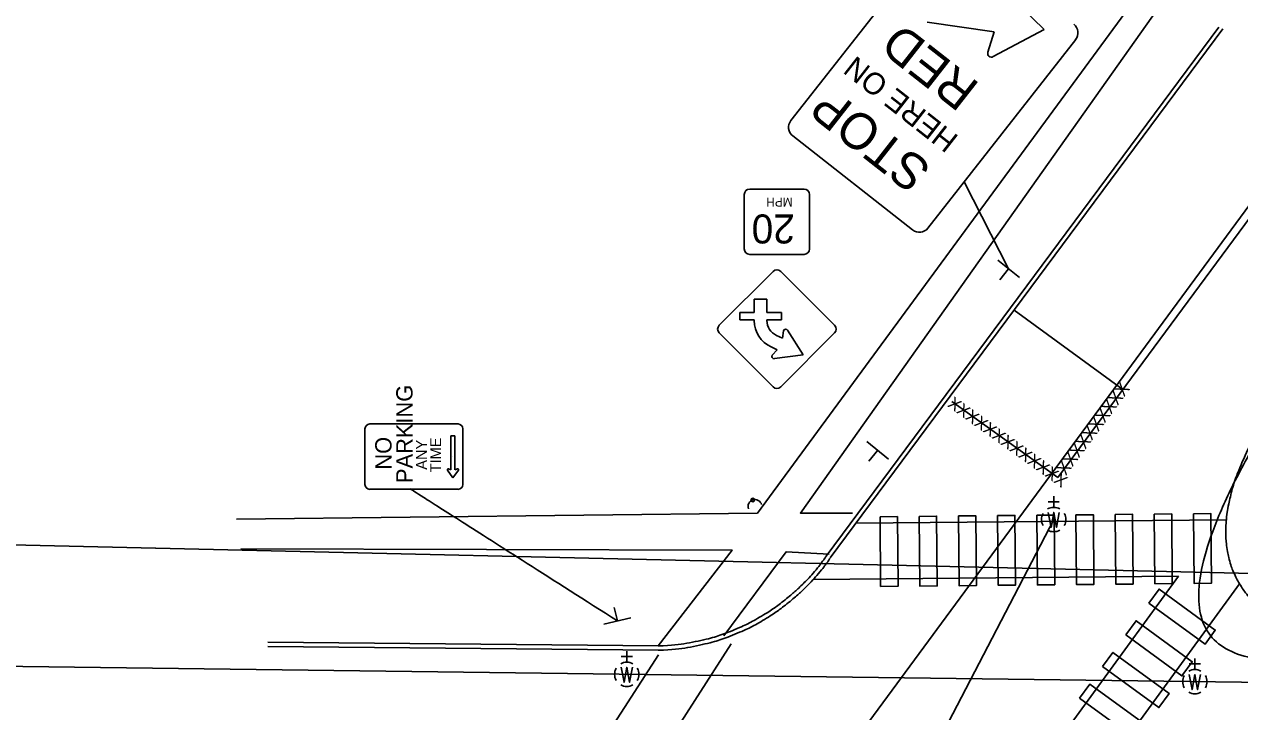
# Model space of a CAD drawing. Extents: x 108269 to 109415, y 548506 to 548874.
# Drawn here: x 108929.7 to 109069.3, y 548713.3 to 548792.2 of the extents above; entities that cross this region are included whole.
import ezdxf

# ---------------------------------------------------------------- set-up
doc = ezdxf.new("R2010")
doc.units = 0
for name, color, linetype in [('Default', 7, 'Continuous'), ('PM_P_Crosswalk', 7, 'Continuous'), ('PM_P_Stop_Line', 7, 'Continuous'), ('SH_Data', 7, 'Continuous'), ('SH_Text', 7, 'Continuous'), ('SN_P_Post', 7, 'Continuous'), ('SN_P_Signs', 7, 'Continuous'), ('SN_P_Text', 7, 'Continuous'), ('SN_X_Post', 7, 'Continuous'), ('SN_X_Public', 7, 'Continuous')]:
    doc.layers.add(name, color=color, linetype=linetype)

msp = doc.modelspace()

# ---------------------------------------------------------------- linework, layer by layer
at = {"layer": 'Default'}
for p, q in [((109022.45, 548706.36), (109144.06, 548871.47)), ((109066.95, 548791.92), (109021.83, 548731.18)), ((109067.41, 548791.7), (109022.29, 548730.97)), ((109048.43, 548740.21), (109081.46, 548784.86)), ((109036.25, 548748.92), (109048.43, 548740.21)), ((109047.97, 548736.78), (109047.97, 548738.05)), ((109048.61, 548737.41), (109047.34, 548737.41)), ((109013.34, 548668.7), (109047.97, 548735.38)), ((109067.8, 548735.36), (109025.26, 548734.96)), ((109047.97, 548735.38), (109047.97, 548735.38)), ((108915.58, 548732.79), (109082.36, 548728.91)), ((109062.3, 548728.89), (109020.34, 548728.49)), ((109062.3, 548728.89), (109034.32, 548690.49)), ((109069.3, 548728.02), (109040.71, 548688.79)), ((108957.71, 548721.32), (109002.57, 548720.87)), ((108957.7, 548720.82), (109002.57, 548720.37)), ((109002.56, 548719.87), (108979.51, 548684.16)), ((109010.93, 548721.11), (108986.03, 548682.43)), ((108998.93, 548719.01), (108998.93, 548720.28)), ((108918.1, 548718.65), (109208.22, 548714.91)), ((108999.57, 548719.65), (108998.3, 548719.65)), ((109064.81, 548718.8), (109063.54, 548718.8)), ((109064.18, 548718.17), (109064.18, 548719.44)), ((108998.93, 548717.61), (108998.93, 548717.61)), ((109064.18, 548716.77), (109064.18, 548716.77))]:
    msp.add_line(p, q, dxfattribs=at)
for points in [[(108954.1, 548735.42), (109013.93, 548736.13), (109058.46, 548796.73)], [(109060.66, 548795.08), (109018.88, 548736.13), (109024.87, 548736.13)], [(109047.34, 548736.2), (109047.66, 548734.47), (109047.97, 548736.2), (109048.29, 548734.47), (109048.61, 548736.2)], [(108954.62, 548732.02), (109011.02, 548731.87), (109002.55, 548720.87)], [(109010.08, 548722.03), (109017.23, 548731.66), (109022.18, 548731.4)], [(108998.3, 548718.43), (108998.62, 548716.71), (108998.93, 548718.43), (108999.25, 548716.71), (108999.57, 548718.43)], [(109063.54, 548717.59), (109063.86, 548715.86), (109064.18, 548717.59), (109064.5, 548715.86), (109064.81, 548717.59)]]:
    msp.add_lwpolyline(points, dxfattribs=at)
msp.add_circle((109013.41, 548737.63), 0.2, dxfattribs=at)
for centre, radius, start, end in [((109013.66, 548736.87), 0.8, 17.6188, 197.6188), ((109047.97, 548735.38), 1.4, 60.0184, 120.0157), ((109047.97, 548735.38), 1.4, 150.0184, 209.9816), ((109047.97, 548735.38), 1.4, 330.0184, 29.9816), ((109047.97, 548735.38), 1.4, 239.9843, 299.9816), ((108998.93, 548717.61), 1.4, 60.0184, 120.0157), ((108998.93, 548717.61), 1.4, 150.0184, 209.9816), ((108998.93, 548717.61), 1.4, 330.0184, 29.9816), ((109064.18, 548716.77), 1.4, 150.0184, 209.9816), ((109064.18, 548716.77), 1.4, 60.0184, 120.0157), ((109064.18, 548716.77), 1.4, 330.0184, 29.9816), ((108998.93, 548717.61), 1.4, 239.9843, 299.9816), ((109064.18, 548716.77), 1.4, 239.9843, 299.9816)]:
    msp.add_arc(centre, radius, start, end, dxfattribs=at)
for points, degree in [([(109072.63, 548746.68), (109055.79, 548718.85), (109092.93, 548719.74), (109092.93, 548719.74)], 2), ([(109072.2, 548746.94), (109071.14, 548745.18), (109070.28, 548743.54), (109068.95, 548740.44), (109068.48, 548739), (109068.02, 548736.97), (109067.9, 548736.31), (109067.76, 548735.05), (109067.73, 548734.44), (109067.74, 548733.27), (109067.78, 548732.7), (109067.93, 548731.62), (109068.05, 548731.09), (109068.33, 548730.09), (109068.51, 548729.61), (109068.92, 548728.69), (109069.15, 548728.25), (109069.67, 548727.42), (109069.96, 548727.02), (109070.58, 548726.26), (109070.91, 548725.9), (109071.96, 548724.89), (109072.73, 548724.28), (109074.39, 548723.2), (109075.27, 548722.73), (109077.1, 548721.9), (109078.05, 548721.54), (109079.96, 548720.92), (109080.92, 548720.66), (109082.82, 548720.21), (109083.76, 548720.03), (109085.57, 548719.74), (109086.44, 548719.62), (109088.89, 548719.36), (109090.29, 548719.28), (109091.8, 548719.24), (109092.2, 548719.23), (109092.63, 548719.23), (109092.74, 548719.23), (109092.85, 548719.24), (109092.88, 548719.24), (109092.91, 548719.24), (109092.92, 548719.24), (109092.93, 548719.24), (109092.93, 548719.24), (109092.94, 548719.24), (109092.94, 548719.24), (109092.94, 548719.24)], 3), ([(109021.83, 548731.18), (109021.83, 548731.18), (109021.83, 548731.18), (109021.83, 548731.18), (109021.83, 548731.18), (109021.83, 548731.17), (109021.82, 548731.17), (109021.81, 548731.14), (109021.79, 548731.11), (109021.72, 548731), (109021.64, 548730.9), (109021.35, 548730.49), (109021.06, 548730.1), (109020.28, 548729.16), (109019.79, 548728.61), (109018.6, 548727.43), (109017.91, 548726.8), (109016.31, 548725.53), (109015.42, 548724.9), (109013.41, 548723.7), (109012.31, 548723.14), (109009.89, 548722.16), (109008.57, 548721.74), (109005.72, 548721.12), (109004.18, 548720.92), (109002.53, 548720.87)], 3), ([(109021.83, 548731.18), (109021.83, 548731.18), (109021.83, 548731.18), (109021.83, 548731.18)], 2), ([(109002.55, 548720.37), (109004.24, 548720.42), (109005.82, 548720.63), (109008.76, 548721.27), (109010.11, 548721.7), (109012.6, 548722.72), (109013.74, 548723.3), (109015.79, 548724.54), (109016.7, 548725.2), (109018.33, 548726.5), (109019.03, 548727.15), (109020.23, 548728.35), (109020.73, 548728.91), (109021.52, 548729.87), (109021.81, 548730.26), (109022.09, 548730.66), (109022.16, 548730.76), (109022.22, 548730.87), (109022.24, 548730.89), (109022.25, 548730.91), (109022.26, 548730.92), (109022.26, 548730.92), (109022.26, 548730.92), (109022.26, 548730.92), (109022.26, 548730.92), (109022.26, 548730.92), (109022.26, 548730.92), (109022.26, 548730.92), (109022.26, 548730.92)], 3), ([(109022.26, 548730.92), (109022.26, 548730.92), (109022.26, 548730.92), (109022.26, 548730.92)], 2)]:
    msp.add_open_spline(points, degree=degree, dxfattribs=at)
at = {"layer": 'PM_P_Crosswalk'}
for points in [[(109028.02, 548735.7), (109030.02, 548735.72), (109030.09, 548727.72), (109028.09, 548727.71)], [(109032.52, 548735.75), (109034.52, 548735.77), (109034.59, 548727.77), (109032.59, 548727.75)], [(109037.02, 548735.79), (109039.02, 548735.81), (109039.09, 548727.81), (109037.09, 548727.79)], [(109041.52, 548735.83), (109043.52, 548735.85), (109043.59, 548727.85), (109041.59, 548727.84)], [(109046.02, 548735.88), (109048.02, 548735.9), (109048.09, 548727.9), (109046.09, 548727.88)], [(109050.52, 548735.92), (109052.52, 548735.94), (109052.59, 548727.94), (109050.59, 548727.92)], [(109055.02, 548735.96), (109057.02, 548735.98), (109057.09, 548727.98), (109055.09, 548727.97)], [(109059.52, 548736.01), (109061.52, 548736.03), (109061.59, 548728.03), (109059.59, 548728.01)], [(109064.02, 548736.05), (109066.02, 548736.07), (109066.09, 548728.07), (109064.09, 548728.05)], [(109058.89, 548725.78), (109060.07, 548727.4), (109066.53, 548722.69), (109065.35, 548721.07)], [(109056.24, 548722.15), (109057.42, 548723.76), (109063.88, 548719.05), (109062.7, 548717.44)], [(109053.59, 548718.51), (109054.77, 548720.13), (109061.23, 548715.41), (109060.05, 548713.8)], [(109050.94, 548714.87), (109052.12, 548716.49), (109058.58, 548711.78), (109057.4, 548710.16)]]:
    msp.add_lwpolyline(points, close=True, dxfattribs=at)
at = {"layer": 'PM_P_Stop_Line'}
msp.add_line((109043.43, 548759.43), (109055.9, 548750.31), dxfattribs=at)
at = {"layer": 'SH_Data'}
msp.add_open_spline([(108997.85, 548723.74), (108974.15, 548738.85), (108974.15, 548738.85), (108974.15, 548738.85)], degree=2, dxfattribs=at)
at = {"layer": 'SH_Text'}
msp.add_line((109042.79, 548764.15), (109037.69, 548774.16), dxfattribs=at)
at = {"layer": 'SN_P_Post'}
for p, q in [((109041.54, 548765.15), (109044.04, 548763.15)), ((109042.79, 548764.15), (109041.79, 548762.9)), ((109042.79, 548764.15), (109042.79, 548764.15))]:
    msp.add_line(p, q, dxfattribs=at)
at = {"layer": 'SN_P_Signs'}
for p, q in [((109034.75, 548802.82), (109017.78, 548781.18)), ((109042.11, 548796.29), (109046.86, 548791.65)), ((109041.14, 548791.37), (109033.42, 548792.46)), ((109040.41, 548789.02), (109041.14, 548791.37)), ((109046.86, 548791.65), (109041.01, 548788.52)), ((109033.52, 548768.84), (109050.49, 548790.48)), ((109017.99, 548779.42), (109031.76, 548768.63)), ((109033.51, 548768.84), (109033.52, 548768.84))]:
    msp.add_line(p, q, dxfattribs=at)
for centre, radius, start, end in [((109049.5, 548791.25), 1.25, 321.8936, 51.8936), ((109040.8, 548788.88), 0.417, 159.8639, 300.4822), ((109018.76, 548780.41), 1.25, 141.8936, 231.8936), ((109032.53, 548769.61), 1.25, 231.8936, 321.8936)]:
    msp.add_arc(centre, radius, start, end, dxfattribs=at)
at = {"layer": 'SN_X_Post'}
for p, q in [((109026.52, 548744.34), (109029.01, 548742.33)), ((109027.76, 548743.34), (109026.75, 548742.09)), ((109027.76, 548743.34), (109027.76, 548743.34)), ((108999.4, 548724.11), (108996.29, 548723.38)), ((108997.85, 548723.74), (108997.48, 548725.3)), ((108997.85, 548723.74), (108997.85, 548723.74))]:
    msp.add_line(p, q, dxfattribs=at)
at = {"layer": 'SN_X_Public'}
for p, q in [((109019.3, 548773.32), (109013.05, 548773.32)), ((109012.42, 548772.7), (109012.42, 548766.45)), ((109019.92, 548766.45), (109019.92, 548772.7)), ((109013.05, 548765.82), (109019.3, 548765.82)), ((109015.03, 548760.68), (109013.57, 548760.68)), ((109013.57, 548760.68), (109013.57, 548759.15)), ((109015.03, 548759.15), (109015.03, 548760.68)), ((109013.57, 548759.15), (109011.9, 548759.15)), ((109011.9, 548759.15), (109011.9, 548758.32)), ((109016.7, 548759.15), (109015.03, 548759.15)), ((109016.7, 548758.32), (109016.7, 548759.15)), ((109011.9, 548758.32), (109013.57, 548758.32)), ((109013.57, 548758.32), (109013.57, 548758.22)), ((109015.03, 548758.22), (109015.03, 548758.32)), ((109015.03, 548758.32), (109016.7, 548758.32)), ((109016.82, 548756.19), (109016.12, 548756.51)), ((109016.94, 548757.04), (109016.82, 548756.19)), ((109019.2, 548754.29), (109017.4, 548757.11)), ((109015.51, 548755.19), (109016.19, 548754.87)), ((109016.19, 548754.87), (109015.64, 548754.24)), ((109015.89, 548753.85), (109019.2, 548754.29)), ((109015.89, 548753.85), (109015.89, 548753.85)), ((108979.2, 548745.01), (108978.74, 548745.01)), ((108979.2, 548741.1), (108979.2, 548745.01)), ((108978.97, 548742.58), (108978.97, 548742.58)), ((108978.35, 548741.05), (108978.97, 548740.16)), ((108978.74, 548741.1), (108978.45, 548741.19)), ((108978.97, 548740.16), (108979.59, 548741.05)), ((108979.49, 548741.19), (108979.2, 548741.1)), ((108979.2, 548741.1), (108979.2, 548741.1))]:
    msp.add_line(p, q, dxfattribs=at)
for points in [[(109009.55, 548757.69), (109015.73, 548763.87)], [(109016.62, 548763.87), (109022.8, 548757.69)], [(109015.73, 548750.61), (109009.55, 548756.8)], [(109022.8, 548756.8), (109016.62, 548750.61)], [(108979.55, 548746.35), (108969.42, 548746.35)], [(108968.86, 548745.79), (108968.86, 548739.41)], [(108978.74, 548745.01), (108978.74, 548741.1)], [(108980.11, 548739.41), (108980.11, 548745.79)], [(108969.42, 548738.85), (108979.55, 548738.85)]]:
    msp.add_lwpolyline(points, dxfattribs=at)
for centre, radius, start, end in [((109013.05, 548772.7), 0.625, 90, 180), ((109019.3, 548772.7), 0.625, 360, 90), ((109013.05, 548766.45), 0.625, 180, 270), ((109019.3, 548766.45), 0.625, 270, 360), ((109016.17, 548763.43), 0.625, 45, 135), ((109009.99, 548757.24), 0.625, 135, 225), ((109016.9, 548758.22), 3.33, 180, 245.2561), ((109016.9, 548758.22), 1.87, 180, 245.2561), ((109022.36, 548757.24), 0.625, 315, 45), ((109017.19, 548756.97), 0.256, 31.989, 164.2151), ((109015.85, 548754.1), 0.256, 145.7849, 278.011), ((109016.17, 548751.06), 0.625, 225, 315), ((108969.42, 548745.79), 0.562, 90, 180), ((108979.55, 548745.79), 0.562, 0, 90), ((108978.42, 548741.1), 0.0912, 72.3622, 215.0792), ((108979.52, 548741.1), 0.0912, 324.9207, 107.6378), ((108969.42, 548739.41), 0.562, 180, 270), ((108979.55, 548739.41), 0.562, 270, 0)]:
    msp.add_arc(centre, radius, start, end, dxfattribs=at)

# ---------------------------------------------------------------- texts
at = {"layer": 'SN_P_Signs'}
for s, height, p in [('RED', 4.15, (109039.61, 548785.32)), ('HERE ON', 2.5, (109037.17, 548779.32)), ('STOP', 4.15, (109034.12, 548775.9))]:
    msp.add_text(s, height=height, rotation=141.8936, dxfattribs=at).set_placement(p)
at = {"layer": 'SN_P_Text'}
for s, rotation, p in [('XXXXXXXXXX', 53.4964, (109049.36, 548740.37)), ('XXXXXXXXXXXXX', 324.416, (109035.69, 548748.43))]:
    msp.add_text(s, height=1.4, rotation=rotation, dxfattribs=at).set_placement(p)
at = {"layer": 'SN_X_Public'}
for s, height, rotation, p in [('MPH', 1.021, 180, (109017.98, 548772.33)), ('20', 3.333, 180, (109018.23, 548770.41)), ('PARKING', 1.875, 90, (108974.33, 548739.57)), ('NO', 1.875, 90, (108971.91, 548741.11)), ('ANY', 1.25, 90, (108975.97, 548741.1)), ('TIME', 1.25, 90, (108977.61, 548740.8))]:
    msp.add_text(s, height=height, rotation=rotation, dxfattribs=at).set_placement(p)

doc.saveas('drawing.dxf')
